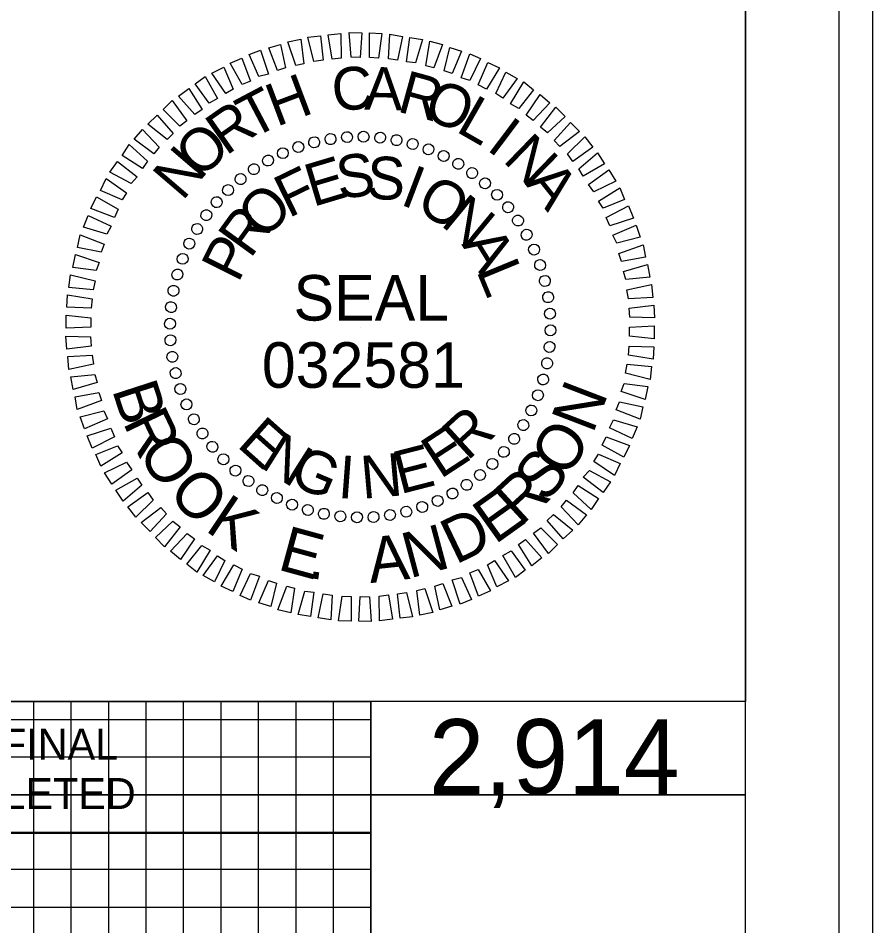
# Model space of a CAD drawing. Extents: x 1191114 to 1192543, y 893004 to 894332.
# Drawn here: x 1191793.56 to 1191839.19, y 894255.3 to 894303.74 of the extents above; entities that cross this region are included whole.
import ezdxf

# ---------------------------------------------------------------- set-up
doc = ezdxf.new("R2010")
doc.units = 0
for name, color, linetype in [('Exist Vertical Profile Ground Line', 7, 'Continuous'), ('Prop Grid Mask', 7, 'Continuous'), ('Sheet DOT Grid CELL', 7, 'Continuous'), ('Sheet Layout Profile Border Port 1', 7, 'Continuous'), ('Sheet PE Seal Cell', 7, 'Continuous'), ('Sheet Plot Border Inside CELL', 7, 'Continuous'), ('Sheet Plot Border Outside CELL', 7, 'Continuous'), ('Sheet Profile CELL', 7, 'Continuous'), ('Sheet Profile Grid Major CELL', 7, 'Continuous'), ('Sheet Profile Grid Middle CELL', 7, 'Continuous'), ('Sheet Profile Grid Minor CELL', 7, 'Continuous')]:
    doc.layers.add(name, color=color, linetype=linetype)

msp = doc.modelspace()

# ---------------------------------------------------------------- linework, layer by layer
at = {"layer": 'Prop Grid Mask'}
for p, q in [((1191752.366, 894267.279), (1191812.378, 894267.279)), ((1191812.378, 894267.275), (1191812.378, 894260.225)), ((1191812.378, 894260.229), (1191752.366, 894260.229))]:
    msp.add_line(p, q, dxfattribs=at)
msp.add_lwpolyline([(1191752.366, 894267.279), (1191812.378, 894267.279), (1191812.378, 894260.229), (1191752.366, 894260.229)], close=True, dxfattribs=at)
at = {"layer": 'Sheet DOT Grid CELL'}
for p, q in [((1191812.386, 894122.299), (1191812.386, 894267.279)), ((1191832.386, 894262.299), (1191232.386, 894262.299))]:
    msp.add_line(p, q, dxfattribs=at)
at = {"layer": 'Sheet Layout Profile Border Port 1'}
msp.add_lwpolyline([(1191252.386, 894322.299), (1191252.386, 894122.299), (1191812.386, 894122.299), (1191812.386, 894267.279), (1191752.366, 894267.279), (1191752.366, 894322.299)], close=True, dxfattribs=at)
at = {"layer": 'Sheet PE Seal Cell'}
for p, q in [((1191811.114, 894297.403), (1191811.114, 894297.403)), ((1191812.005, 894297.423), (1191812.005, 894297.423)), ((1191812.896, 894297.363), (1191812.896, 894297.363)), ((1191808.501, 894296.877), (1191808.501, 894296.877)), ((1191809.352, 894297.12), (1191809.352, 894297.12)), ((1191810.243, 894297.282), (1191810.243, 894297.282)), ((1191813.766, 894297.221), (1191813.766, 894297.221)), ((1191814.617, 894297.039), (1191814.617, 894297.039)), ((1191807.691, 894296.553), (1191807.691, 894296.553)), ((1191815.467, 894296.755), (1191815.467, 894296.755)), ((1191816.277, 894296.391), (1191816.277, 894296.391)), ((1191806.902, 894296.148), (1191806.902, 894296.148)), ((1191817.067, 894295.986), (1191817.067, 894295.986)), ((1191806.132, 894295.682), (1191806.132, 894295.682)), ((1191817.796, 894295.479), (1191817.796, 894295.479)), ((1191805.423, 894295.176), (1191805.423, 894295.176)), ((1191818.505, 894294.933), (1191818.505, 894294.933)), ((1191804.755, 894294.568), (1191804.755, 894294.568)), ((1191804.148, 894293.94), (1191804.148, 894293.94)), ((1191819.133, 894294.325), (1191819.133, 894294.325)), ((1191819.74, 894293.657), (1191819.74, 894293.657)), ((1191803.601, 894293.232), (1191803.601, 894293.232)), ((1191820.246, 894292.948), (1191820.246, 894292.948)), ((1191803.095, 894292.503), (1191803.095, 894292.503)), ((1191820.712, 894292.179), (1191820.712, 894292.179)), ((1191802.69, 894291.713), (1191802.69, 894291.713)), ((1191821.117, 894291.389), (1191821.117, 894291.389)), ((1191802.325, 894290.903), (1191802.325, 894290.903)), ((1191821.441, 894290.579), (1191821.441, 894290.579)), ((1191802.042, 894290.052), (1191802.042, 894290.052)), ((1191821.684, 894289.728), (1191821.684, 894289.728)), ((1191801.859, 894289.202), (1191801.859, 894289.202)), ((1191821.846, 894288.837), (1191821.846, 894288.837)), ((1191801.718, 894288.331), (1191801.718, 894288.331)), ((1191821.968, 894287.967), (1191821.968, 894287.967)), ((1191801.657, 894287.44), (1191801.657, 894287.44)), ((1191811.822, 894287.258), (1191811.822, 894287.258)), ((1191821.988, 894287.076), (1191821.988, 894287.076)), ((1191801.677, 894286.549), (1191801.677, 894286.549)), ((1191821.927, 894286.185), (1191821.927, 894286.185)), ((1191801.799, 894285.678), (1191801.799, 894285.678)), ((1191821.785, 894285.314), (1191821.785, 894285.314)), ((1191801.961, 894284.787), (1191801.961, 894284.787)), ((1191821.603, 894284.463), (1191821.603, 894284.463)), ((1191802.204, 894283.937), (1191802.204, 894283.937)), ((1191821.32, 894283.613), (1191821.32, 894283.613)), ((1191802.528, 894283.127), (1191802.528, 894283.127)), ((1191820.955, 894282.803), (1191820.955, 894282.803)), ((1191802.933, 894282.337), (1191802.933, 894282.337)), ((1191820.55, 894282.013), (1191820.55, 894282.013)), ((1191803.398, 894281.568), (1191803.398, 894281.568)), ((1191803.905, 894280.859), (1191803.905, 894280.859)), ((1191820.044, 894281.284), (1191820.044, 894281.284)), ((1191819.497, 894280.575), (1191819.497, 894280.575)), ((1191804.512, 894280.191), (1191804.512, 894280.191)), ((1191818.89, 894279.948), (1191818.89, 894279.948)), ((1191805.14, 894279.583), (1191805.14, 894279.583)), ((1191805.849, 894279.036), (1191805.849, 894279.036)), ((1191818.221, 894279.34), (1191818.221, 894279.34)), ((1191806.578, 894278.53), (1191806.578, 894278.53)), ((1191817.513, 894278.834), (1191817.513, 894278.834)), ((1191807.367, 894278.125), (1191807.367, 894278.125)), ((1191815.953, 894277.963), (1191815.953, 894277.963)), ((1191816.743, 894278.368), (1191816.743, 894278.368)), ((1191808.177, 894277.761), (1191808.177, 894277.761)), ((1191809.028, 894277.477), (1191809.028, 894277.477)), ((1191815.143, 894277.639), (1191815.143, 894277.639)), ((1191809.878, 894277.295), (1191809.878, 894277.295)), ((1191810.749, 894277.153), (1191810.749, 894277.153)), ((1191811.64, 894277.092), (1191811.64, 894277.092)), ((1191812.531, 894277.113), (1191812.531, 894277.113)), ((1191813.402, 894277.234), (1191813.402, 894277.234)), ((1191814.293, 894277.396), (1191814.293, 894277.396))]:
    msp.add_line(p, q, dxfattribs=at)
for points in [[(1191808.38, 894301.21), (1191807.955, 894302.486), (1191808.643, 894302.628), (1191808.805, 894301.311)], [(1191809.352, 894301.433), (1191809.028, 894302.729), (1191809.696, 894302.79), (1191809.838, 894301.494)], [(1191810.324, 894301.554), (1191810.101, 894302.85), (1191810.79, 894302.931), (1191810.81, 894301.615)], [(1191811.336, 894301.656), (1191811.235, 894302.972), (1191811.903, 894302.952), (1191811.822, 894301.635)], [(1191812.308, 894301.635), (1191812.308, 894302.952), (1191812.977, 894302.931), (1191812.794, 894301.615)], [(1191813.321, 894301.575), (1191813.402, 894302.891), (1191814.07, 894302.769), (1191813.807, 894301.494)], [(1191814.293, 894301.413), (1191814.475, 894302.709), (1191815.143, 894302.607), (1191814.779, 894301.352)], [(1191807.408, 894300.947), (1191806.942, 894302.162), (1191807.57, 894302.344), (1191807.833, 894301.089)], [(1191815.326, 894301.19), (1191815.528, 894302.506), (1191816.217, 894302.344), (1191815.751, 894301.089)], [(1191816.298, 894300.927), (1191816.601, 894302.182), (1191817.229, 894301.98), (1191816.723, 894300.785)], [(1191806.416, 894300.623), (1191805.889, 894301.797), (1191806.497, 894302.04), (1191806.922, 894300.744)], [(1191817.209, 894300.562), (1191817.675, 894301.838), (1191818.242, 894301.595), (1191817.675, 894300.42)], [(1191805.525, 894300.198), (1191804.877, 894301.332), (1191805.504, 894301.615), (1191805.97, 894300.38)], [(1191818.12, 894300.177), (1191818.626, 894301.372), (1191819.254, 894301.089), (1191818.566, 894299.955)], [(1191804.654, 894299.712), (1191803.905, 894300.805), (1191804.532, 894301.129), (1191805.039, 894299.955)], [(1191819.052, 894299.712), (1191819.598, 894300.866), (1191820.206, 894300.522), (1191819.436, 894299.469)], [(1191803.763, 894299.205), (1191803.014, 894300.238), (1191803.54, 894300.623), (1191804.208, 894299.448)], [(1191819.841, 894299.165), (1191820.55, 894300.339), (1191821.077, 894299.914), (1191820.287, 894298.922)], [(1191802.993, 894298.598), (1191802.123, 894299.57), (1191802.669, 894299.995), (1191803.378, 894298.861)], [(1191802.183, 894297.97), (1191801.292, 894298.861), (1191801.778, 894299.347), (1191802.568, 894298.254)], [(1191820.672, 894298.557), (1191821.421, 894299.671), (1191821.947, 894299.226), (1191821.056, 894298.274)], [(1191821.441, 894297.93), (1191822.271, 894298.983), (1191822.757, 894298.497), (1191821.826, 894297.626)], [(1191801.515, 894297.261), (1191800.482, 894298.092), (1191800.989, 894298.557), (1191801.839, 894297.585)], [(1191800.806, 894296.492), (1191799.753, 894297.282), (1191800.199, 894297.808), (1191801.09, 894296.856)], [(1191822.17, 894297.221), (1191823.041, 894298.173), (1191823.527, 894297.687), (1191822.474, 894296.897)], [(1191822.879, 894296.492), (1191823.81, 894297.403), (1191824.236, 894296.856), (1191823.162, 894296.087)], [(1191800.199, 894295.722), (1191799.105, 894296.411), (1191799.49, 894296.998), (1191800.462, 894296.107)], [(1191823.486, 894295.702), (1191824.479, 894296.553), (1191824.863, 894295.965), (1191823.729, 894295.317)], [(1191799.591, 894294.912), (1191798.457, 894295.52), (1191798.862, 894296.087), (1191799.915, 894295.277)], [(1191824.013, 894294.872), (1191825.086, 894295.641), (1191825.471, 894295.034), (1191824.296, 894294.467)], [(1191799.105, 894294.042), (1191797.951, 894294.548), (1191798.255, 894295.176), (1191799.348, 894294.426)], [(1191824.539, 894293.981), (1191825.673, 894294.69), (1191825.937, 894294.062), (1191824.782, 894293.596)], [(1191798.7, 894293.11), (1191797.445, 894293.576), (1191797.749, 894294.204), (1191798.903, 894293.556)], [(1191824.944, 894293.11), (1191826.139, 894293.718), (1191826.402, 894293.07), (1191825.147, 894292.665)], [(1191798.295, 894292.219), (1191797.04, 894292.584), (1191797.303, 894293.211), (1191798.518, 894292.644)], [(1191825.309, 894292.158), (1191826.544, 894292.685), (1191826.767, 894292.057), (1191825.511, 894291.733)], [(1191797.992, 894291.247), (1191796.736, 894291.51), (1191796.878, 894292.179), (1191798.154, 894291.672)], [(1191825.633, 894291.186), (1191826.929, 894291.652), (1191827.05, 894290.984), (1191825.775, 894290.761)], [(1191797.728, 894290.275), (1191796.473, 894290.437), (1191796.615, 894291.126), (1191797.89, 894290.7)], [(1191825.876, 894290.214), (1191827.152, 894290.599), (1191827.273, 894289.911), (1191825.997, 894289.789)], [(1191797.566, 894289.242), (1191796.27, 894289.364), (1191796.351, 894290.052), (1191797.668, 894289.728)], [(1191826.058, 894289.242), (1191827.374, 894289.526), (1191827.435, 894288.837), (1191826.139, 894288.756)], [(1191797.465, 894288.27), (1191796.149, 894288.311), (1191796.189, 894288.979), (1191797.506, 894288.756)], [(1191826.18, 894288.27), (1191827.496, 894288.432), (1191827.536, 894287.744), (1191826.22, 894287.784)], [(1191797.445, 894287.258), (1191796.129, 894287.197), (1191796.129, 894287.886), (1191797.445, 894287.744)], [(1191826.2, 894287.258), (1191827.516, 894287.319), (1191827.516, 894286.63), (1191826.2, 894286.772)], [(1191797.465, 894286.245), (1191796.149, 894286.083), (1191796.108, 894286.772), (1191797.425, 894286.731)], [(1191826.18, 894286.245), (1191827.496, 894286.205), (1191827.455, 894285.537), (1191826.139, 894285.759)], [(1191797.587, 894285.273), (1191796.27, 894284.99), (1191796.21, 894285.678), (1191797.506, 894285.759)], [(1191826.078, 894285.273), (1191827.374, 894285.152), (1191827.293, 894284.463), (1191825.977, 894284.787)], [(1191797.769, 894284.301), (1191796.493, 894283.917), (1191796.372, 894284.605), (1191797.647, 894284.727)], [(1191825.916, 894284.241), (1191827.172, 894284.079), (1191827.03, 894283.39), (1191825.754, 894283.815)], [(1191798.012, 894283.329), (1191796.716, 894282.864), (1191796.594, 894283.532), (1191797.87, 894283.755)], [(1191825.653, 894283.269), (1191826.909, 894283.005), (1191826.767, 894282.337), (1191825.491, 894282.843)], [(1191798.336, 894282.357), (1191797.101, 894281.831), (1191796.878, 894282.459), (1191798.133, 894282.783)], [(1191825.349, 894282.297), (1191826.605, 894281.932), (1191826.342, 894281.304), (1191825.127, 894281.871)], [(1191798.7, 894281.406), (1191797.506, 894280.798), (1191797.242, 894281.446), (1191798.498, 894281.851)], [(1191824.944, 894281.406), (1191826.2, 894280.94), (1191825.896, 894280.312), (1191824.742, 894280.96)], [(1191799.105, 894280.535), (1191797.971, 894279.826), (1191797.708, 894280.454), (1191798.862, 894280.92)], [(1191824.539, 894280.474), (1191825.694, 894279.968), (1191825.39, 894279.34), (1191824.296, 894280.089)], [(1191799.632, 894279.644), (1191798.559, 894278.874), (1191798.174, 894279.482), (1191799.348, 894280.049)], [(1191824.053, 894279.603), (1191825.187, 894278.996), (1191824.782, 894278.429), (1191823.729, 894279.239)], [(1191800.158, 894278.814), (1191799.166, 894277.963), (1191798.781, 894278.55), (1191799.915, 894279.198)], [(1191800.766, 894278.024), (1191799.834, 894277.113), (1191799.409, 894277.659), (1191800.482, 894278.429)], [(1191823.446, 894278.793), (1191824.539, 894278.105), (1191824.155, 894277.518), (1191823.183, 894278.409)], [(1191822.838, 894278.024), (1191823.891, 894277.234), (1191823.446, 894276.708), (1191822.555, 894277.659)], [(1191801.475, 894277.295), (1191800.604, 894276.343), (1191800.118, 894276.829), (1191801.171, 894277.619)], [(1191822.13, 894277.254), (1191823.162, 894276.424), (1191822.656, 894275.958), (1191821.806, 894276.93)], [(1191802.204, 894276.586), (1191801.373, 894275.533), (1191800.887, 894276.019), (1191801.819, 894276.89)], [(1191821.461, 894276.546), (1191822.352, 894275.655), (1191821.866, 894275.169), (1191821.077, 894276.262)], [(1191802.973, 894275.958), (1191802.224, 894274.845), (1191801.697, 894275.29), (1191802.588, 894276.242)], [(1191803.803, 894275.351), (1191803.095, 894274.176), (1191802.568, 894274.602), (1191803.358, 894275.594)], [(1191820.651, 894275.918), (1191821.522, 894274.946), (1191820.975, 894274.521), (1191820.267, 894275.655)], [(1191804.593, 894274.804), (1191804.046, 894273.65), (1191803.439, 894273.994), (1191804.208, 894275.047)], [(1191819.882, 894275.31), (1191820.631, 894274.278), (1191820.105, 894273.893), (1191819.436, 894275.067)], [(1191805.525, 894274.338), (1191805.018, 894273.144), (1191804.391, 894273.427), (1191805.079, 894274.561)], [(1191818.991, 894274.804), (1191819.74, 894273.711), (1191819.112, 894273.387), (1191818.606, 894274.561)], [(1191806.436, 894273.954), (1191805.97, 894272.678), (1191805.403, 894272.921), (1191805.97, 894274.095)], [(1191818.12, 894274.318), (1191818.768, 894273.184), (1191818.14, 894272.901), (1191817.675, 894274.136)], [(1191807.347, 894273.589), (1191807.043, 894272.334), (1191806.416, 894272.536), (1191806.922, 894273.731)], [(1191816.237, 894273.569), (1191816.703, 894272.354), (1191816.075, 894272.172), (1191815.812, 894273.427)], [(1191817.229, 894273.893), (1191817.756, 894272.718), (1191817.148, 894272.475), (1191816.723, 894273.771)], [(1191808.319, 894273.326), (1191808.117, 894272.01), (1191807.428, 894272.172), (1191807.894, 894273.427)], [(1191809.352, 894273.103), (1191809.17, 894271.807), (1191808.501, 894271.908), (1191808.866, 894273.164)], [(1191814.293, 894273.083), (1191814.617, 894271.787), (1191813.949, 894271.726), (1191813.807, 894273.022)], [(1191815.265, 894273.306), (1191815.69, 894272.03), (1191815.002, 894271.888), (1191814.84, 894273.204)], [(1191810.324, 894272.941), (1191810.243, 894271.625), (1191809.575, 894271.746), (1191809.838, 894273.022)], [(1191811.336, 894272.88), (1191811.336, 894271.564), (1191810.668, 894271.584), (1191810.85, 894272.901)], [(1191812.308, 894272.86), (1191812.41, 894271.544), (1191811.741, 894271.564), (1191811.822, 894272.88)], [(1191813.321, 894272.961), (1191813.544, 894271.665), (1191812.855, 894271.584), (1191812.835, 894272.901)]]:
    msp.add_lwpolyline(points, close=True, dxfattribs=at)
for centre, major_axis in [((1191809.365, 894297.114), (-0.071, 0.283)), ((1191810.233, 894297.29), (-0.046, 0.288)), ((1191811.114, 894297.391), (-0.02, 0.291)), ((1191812, 894297.414), (0.005, 0.292)), ((1191812.884, 894297.36), (0.03, 0.29)), ((1191813.761, 894297.229), (0.056, 0.286)), ((1191814.622, 894297.022), (0.08, 0.28)), ((1191807.691, 894296.537), (-0.119, 0.266)), ((1191808.516, 894296.862), (-0.095, 0.276)), ((1191815.463, 894296.741), (0.105, 0.272)), ((1191806.898, 894296.142), (-0.141, 0.255)), ((1191816.275, 894296.387), (0.128, 0.262)), ((1191806.142, 894295.679), (-0.163, 0.242)), ((1191817.054, 894295.965), (0.15, 0.25)), ((1191805.43, 894295.152), (-0.184, 0.227)), ((1191817.793, 894295.475), (0.171, 0.236)), ((1191804.767, 894294.565), (-0.203, 0.21)), ((1191818.486, 894294.924), (0.191, 0.22)), ((1191819.129, 894294.314), (0.21, 0.203)), ((1191804.157, 894293.922), (-0.22, 0.191)), ((1191819.716, 894293.65), (0.227, 0.184)), ((1191803.605, 894293.228), (-0.236, 0.171)), ((1191820.243, 894292.938), (0.242, 0.163)), ((1191803.116, 894292.489), (-0.25, 0.15)), ((1191820.706, 894292.182), (0.255, 0.141)), ((1191802.693, 894291.711), (-0.262, 0.128)), ((1191821.102, 894291.389), (0.266, 0.119)), ((1191802.34, 894290.898), (-0.272, 0.105)), ((1191821.426, 894290.565), (0.276, 0.095)), ((1191802.059, 894290.058), (-0.28, 0.08)), ((1191821.678, 894289.715), (0.283, 0.071)), ((1191801.852, 894289.196), (-0.286, 0.056)), ((1191821.855, 894288.847), (0.288, 0.046)), ((1191801.721, 894288.32), (-0.29, 0.03)), ((1191821.955, 894287.967), (0.291, 0.02)), ((1191801.667, 894287.435), (-0.292, 0.005)), ((1191821.978, 894287.081), (0.292, -0.005)), ((1191801.69, 894286.549), (-0.291, -0.02)), ((1191821.924, 894286.196), (0.29, -0.03)), ((1191801.79, 894285.669), (-0.288, -0.046)), ((1191821.793, 894285.32), (0.286, -0.056)), ((1191801.967, 894284.801), (-0.283, -0.071)), ((1191821.586, 894284.458), (0.28, -0.08)), ((1191802.218, 894283.951), (-0.276, -0.095)), ((1191821.305, 894283.618), (0.272, -0.105)), ((1191802.543, 894283.127), (-0.266, -0.119)), ((1191820.952, 894282.805), (0.262, -0.128)), ((1191802.939, 894282.334), (-0.255, -0.141)), ((1191820.529, 894282.027), (0.25, -0.15)), ((1191803.402, 894281.578), (-0.242, -0.163)), ((1191820.04, 894281.288), (0.236, -0.171)), ((1191803.929, 894280.866), (-0.227, -0.184)), ((1191819.488, 894280.594), (0.22, -0.191)), ((1191804.516, 894280.202), (-0.21, -0.203)), ((1191805.159, 894279.592), (-0.191, -0.22)), ((1191818.878, 894279.951), (0.203, -0.21)), ((1191805.852, 894279.04), (-0.171, -0.236)), ((1191818.215, 894279.364), (0.184, -0.227)), ((1191806.591, 894278.551), (-0.15, -0.25)), ((1191817.502, 894278.837), (0.163, -0.242)), ((1191807.37, 894278.129), (-0.128, -0.262)), ((1191816.747, 894278.374), (0.141, -0.255)), ((1191808.182, 894277.775), (-0.105, -0.272)), ((1191815.129, 894277.654), (0.095, -0.276)), ((1191815.954, 894277.979), (0.119, -0.266)), ((1191809.023, 894277.494), (-0.08, -0.28)), ((1191809.884, 894277.287), (-0.056, -0.286)), ((1191810.761, 894277.156), (-0.03, -0.29)), ((1191812.531, 894277.125), (0.02, -0.291)), ((1191813.411, 894277.226), (0.046, -0.288)), ((1191814.28, 894277.402), (0.071, -0.283)), ((1191811.645, 894277.102), (-0.005, -0.292))]:
    msp.add_ellipse(centre, major_axis=major_axis, ratio=0.999708, dxfattribs=at)
at = {"layer": 'Sheet Plot Border Inside CELL'}
msp.add_lwpolyline([(1191170.786, 893901.279), (1191837.386, 893901.279), (1191837.386, 894323.319), (1191170.786, 894323.319)], close=True, dxfattribs=at)
at = {"layer": 'Sheet Plot Border Outside CELL'}
msp.add_lwpolyline([(1191165.586, 893892.299), (1191839.186, 893892.299), (1191839.186, 894332.299), (1191165.586, 894332.299)], close=True, dxfattribs=at)
at = {"layer": 'Sheet Profile CELL'}
for points in [[(1191832.386, 894322.299), (1191232.386, 894322.299), (1191232.386, 893902.299), (1191832.386, 893902.299)], [(1191792.386, 894312.279), (1191832.386, 894312.279), (1191832.386, 894267.279), (1191792.386, 894267.279)]]:
    msp.add_lwpolyline(points, close=True, dxfattribs=at)
at = {"layer": 'Sheet Profile Grid Major CELL'}
for points in [[(1191752.386, 894282.299), (1191232.386, 894282.299), (1191232.386, 894262.299), (1191832.386, 894262.299)], [(1191812.386, 894267.279), (1191812.386, 894122.299), (1191832.386, 894122.299), (1191832.386, 894262.299)]]:
    msp.add_lwpolyline(points, dxfattribs=at)
at = {"layer": 'Sheet Profile Grid Middle CELL'}
msp.add_lwpolyline([(1191782.386, 894227.419), (1191782.386, 894122.299), (1191802.386, 894122.299), (1191802.386, 894267.279)], dxfattribs=at)
at = {"layer": 'Sheet Profile Grid Minor CELL'}
for p, q in [((1191812.386, 894266.299), (1191252.386, 894266.299)), ((1191812.386, 894264.299), (1191252.386, 894264.299)), ((1191252.386, 894260.299), (1191812.386, 894260.299)), ((1191812.386, 894258.299), (1191252.386, 894258.299)), ((1191252.386, 894256.299), (1191812.386, 894256.299))]:
    msp.add_line(p, q, dxfattribs=at)
for points in [[(1191794.386, 894267.279), (1191794.386, 894122.299), (1191796.386, 894122.299), (1191796.386, 894267.279)], [(1191798.386, 894267.279), (1191798.386, 894122.299), (1191800.386, 894122.299), (1191800.386, 894267.279)], [(1191804.386, 894267.279), (1191804.386, 894122.299), (1191806.386, 894122.299), (1191806.386, 894267.279)], [(1191808.386, 894267.279), (1191808.386, 894122.299), (1191810.386, 894122.299), (1191810.386, 894267.279)]]:
    msp.add_lwpolyline(points, dxfattribs=at)

# ---------------------------------------------------------------- texts
at = {"layer": 'Exist Vertical Profile Ground Line'}
msp.add_text('2,914', height=4, dxfattribs=at).set_placement((1191815.481, 894262.329))
at = {"layer": 'Prop Grid Mask'}
for s, p in [('DOCUMENT NOT CONSIDERED FINAL', (1191758.688, 894264.175)), ('UNLESS ALL SIGNATURES COMPLETED', (1191757.166, 894261.535))]:
    msp.add_text(s, height=1.65, dxfattribs=at).set_placement(p)
at = {"layer": 'Sheet PE Seal Cell'}
for s, height, rotation, p in [('C', 2.283, 6.2199, (1191810.425, 894298.74)), ('H', 2.283, 20.6195, (1191807.347, 894297.93)), ('A', 2.283, 359.0203, (1191812.025, 894298.861)), ('R', 2.283, 344.6211, (1191813.726, 894298.78)), ('O', 2.283, 337.4212, (1191815.083, 894298.476)), ('T', 2.283, 27.8198, (1191806.031, 894297.261)), ('L', 2.283, 330.2209, (1191816.865, 894297.727)), ('R', 2.284, 35.0205, (1191804.654, 894296.37)), ('I', 2.283, 323.0201, (1191818.505, 894296.755)), ('O', 2.284, 42.2217, (1191803.257, 894295.115)), ('N', 2.284, 315.8189, (1191819.376, 894296.127)), ('N', 2.284, 49.4235, (1191802.325, 894293.94)), ('E', 2.283, 16.6111, (1191809.291, 894293.657)), ('S', 2.283, 7.2556, (1191810.688, 894294.082)), ('S', 2.283, 357.9004, (1191812.146, 894294.102)), ('F', 2.283, 25.967, (1191807.995, 894293.049)), ('I', 2.283, 339.1896, (1191813.888, 894293.819)), ('A', 2.284, 308.6172, (1191820.57, 894294.933)), ('O', 2.283, 329.8335, (1191814.698, 894293.535)), ('O', 2.284, 44.6812, (1191806.659, 894291.855)), ('N', 2.284, 320.4766, (1191816.055, 894292.725)), ('R', 2.284, 54.0397, (1191805.95, 894290.862)), ('P', 2.284, 63.3989, (1191805.302, 894289.566)), ('A', 2.284, 301.7603, (1191817.209, 894291.672)), ('L', 2.284, 292.4008, (1191817.999, 894290.275)), ('SEAL', 2.4293, 360, (1191808.259, 894287.602)), ('B', 2.429, 287.9639, (1191798.556, 894283.92)), ('N', 2.429, 69.007, (1191824.237, 894281.512)), ('R', 2.429, 295.6605, (1191799.123, 894282.174)), ('R', 2.284, 42.4814, (1191817.533, 894280.069)), ('E', 2.283, 318.2769, (1191805.18, 894280.92)), ('E', 2.284, 33.1241, (1191816.095, 894279.117)), ('O', 2.429, 57.4465, (1191822.834, 894279.141)), ('O', 2.429, 303.1407, (1191799.893, 894280.564)), ('N', 2.284, 327.634, (1191806.395, 894279.826)), ('E', 2.283, 14.4118, (1191813.949, 894278.328)), ('G', 2.283, 336.9902, (1191807.934, 894278.915)), ('I', 2.283, 355.7012, (1191810.587, 894278.145)), ('N', 2.283, 5.0564, (1191811.944, 894278.085)), ('S', 2.429, 50.1208, (1191821.709, 894277.803)), ('O', 2.429, 314.7011, (1191801.476, 894278.309)), ('R', 2.429, 42.6406, (1191820.394, 894276.597)), ('E', 2.429, 35.5312, (1191819.008, 894275.618)), ('K', 2.429, 326.2616, (1191803.48, 894276.417)), ('D', 2.429, 25.6554, (1191816.905, 894274.558)), ('E', 2.429, 344.7458, (1191807.347, 894274.331)), ('N', 2.429, 14.9296, (1191814.453, 894273.834)), ('A', 2.429, 6.0893, (1191812.359, 894273.589)), ('.', 2.429, 351.8552, (1191808.981, 894273.877))]:
    msp.add_text(s, height=height, rotation=rotation, dxfattribs=at).set_placement(p)
msp.add_text('032581', height=2.4293, dxfattribs=at).set_placement((1191806.569, 894284.015))

doc.saveas('drawing.dxf')
